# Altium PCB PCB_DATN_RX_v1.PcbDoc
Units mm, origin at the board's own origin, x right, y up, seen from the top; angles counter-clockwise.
Board outline 70.3 x 45.3 mm, 2 copper layers (Top Layer, Bottom Layer); 34 components, 25 nets, 155 pads, 46 vias.
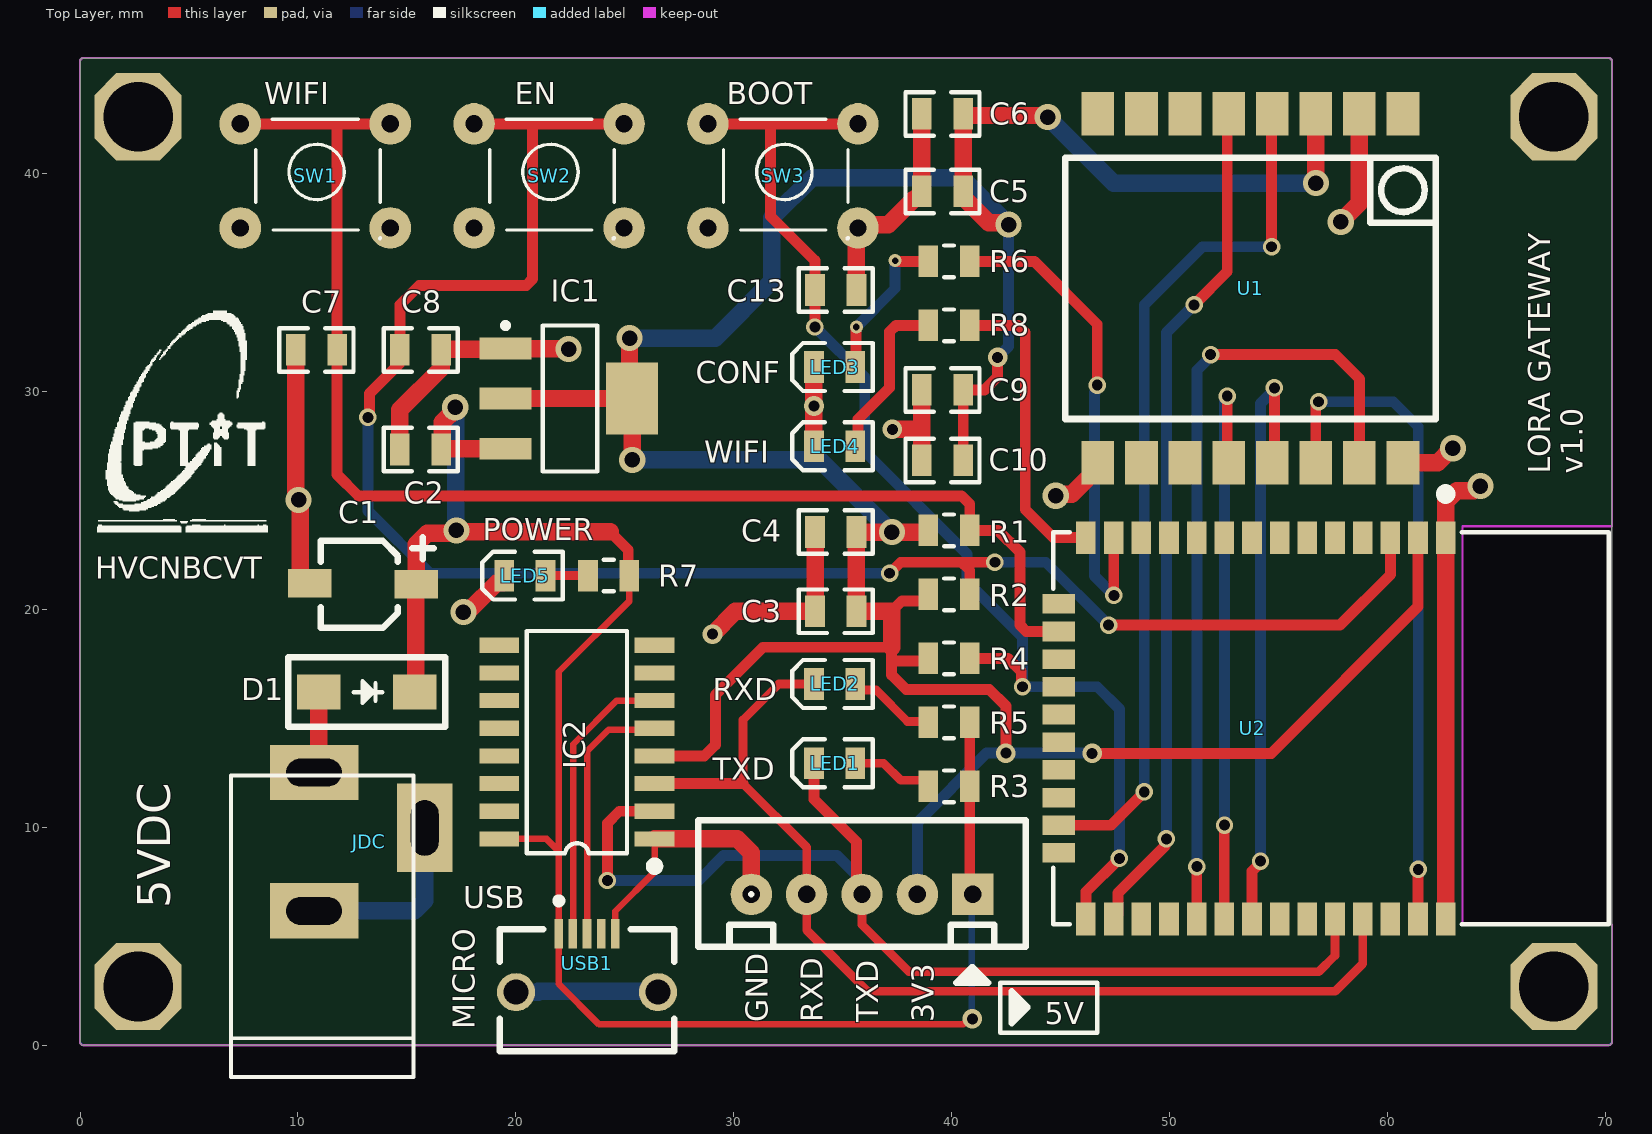
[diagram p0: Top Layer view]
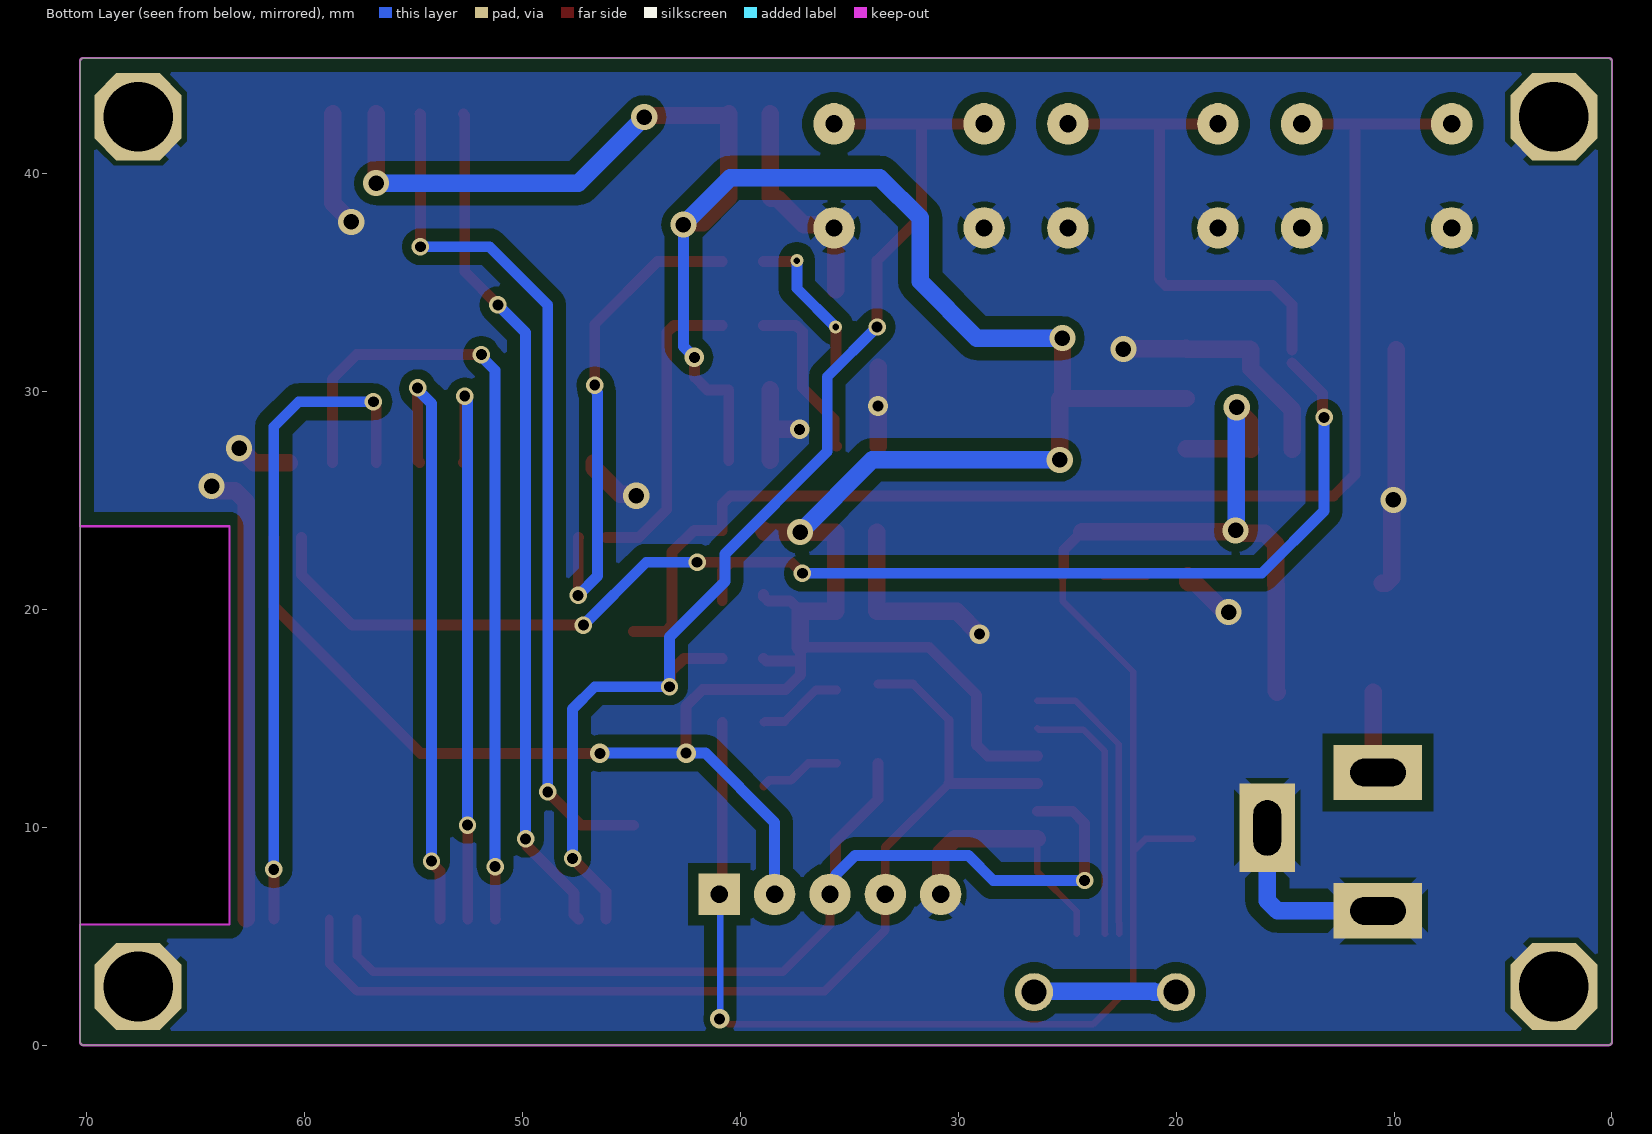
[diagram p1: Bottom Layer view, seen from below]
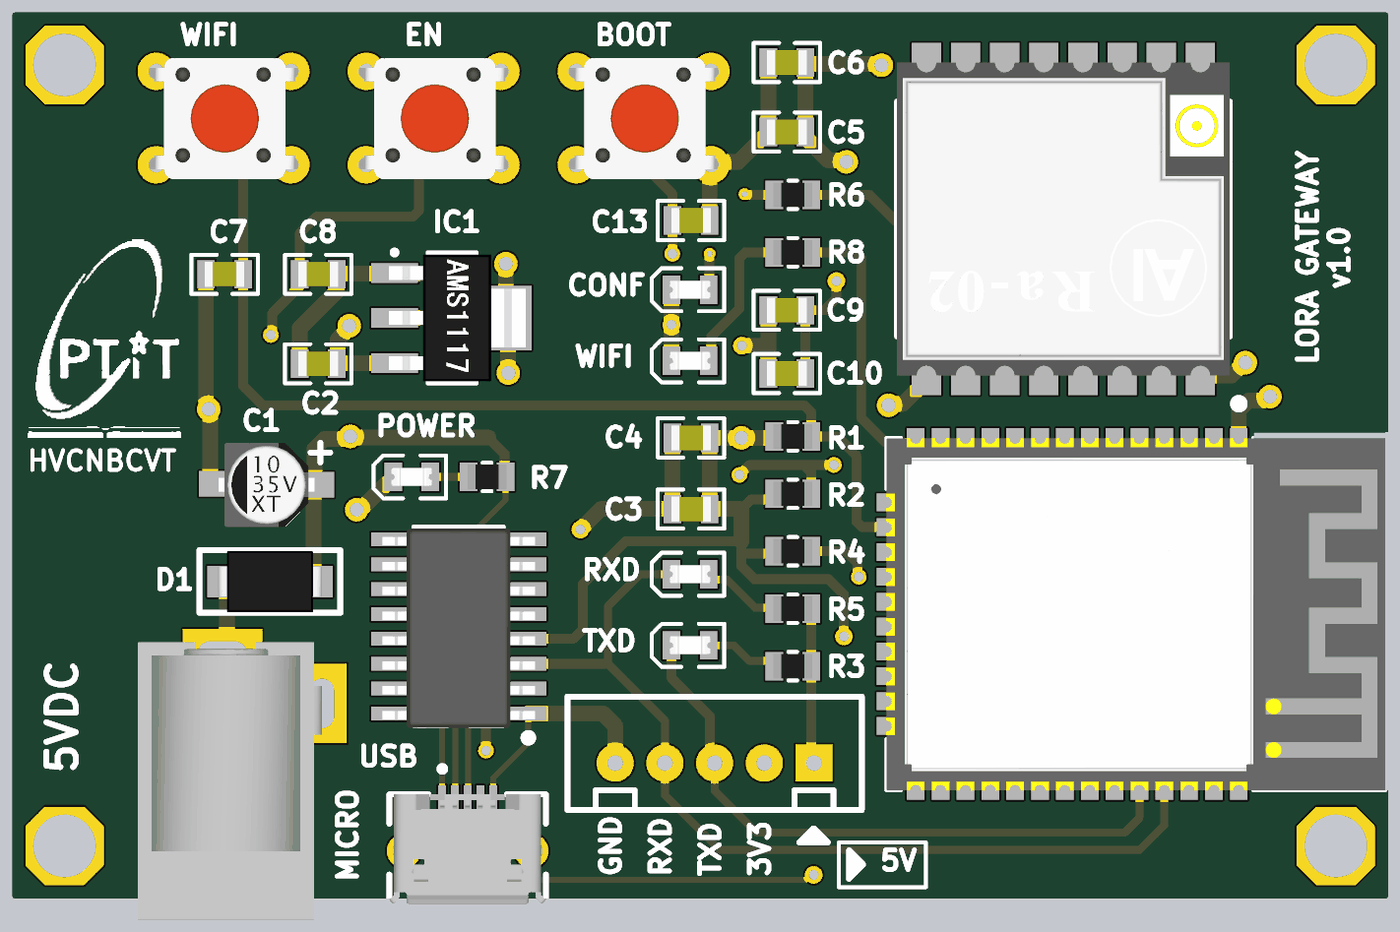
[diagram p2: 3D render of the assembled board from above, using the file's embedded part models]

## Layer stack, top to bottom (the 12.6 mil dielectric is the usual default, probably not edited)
Top Solder: solder mask 0.0102, Solder Resist, Dk 3.5
Top Layer: signal copper 0.0356
Dielectric 1: dielectric 0.32, FR-4, Dk 4.8
Bottom Layer: signal copper 0.0356
Bottom Solder: solder mask 0.0102, Solder Resist, Dk 3.5

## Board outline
0,0.15 ccw(c0.15,0.15) 0.15,0 70.15,0 ccw(c70.15,0.15) 70.301,0.15 70.301,45.15 ccw(c70.15,45.15) 70.15,45.301 0.15,45.301 ccw(c0.15,45.15) 0,45.15
cut-out: 70.301,23.814 63.443,23.814 63.443,5.526 70.301,5.526

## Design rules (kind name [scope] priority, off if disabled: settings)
Clearance [All] p1: gap=0.254 ignorepadtopadclearanceinfootprint=FALSE except(0.3: SMDPad-Fill SMDPad-Poly SMDPad-Region Via-Fill Via-Poly Via-Region Fill-Fill Fill-Poly Fill-Region Poly-Poly Poly-Region Region-Region; 0.5: THPad-Fill THPad-Poly THPad-Region; 0.6: Arc-Fill Arc-Poly Arc-Region Track-Fill Track-Poly Track-Region)
DiffPairsRouting [InDifferentialPair('USB_TX')] p1: maxlimit=0.508 minlimit=0.254 mostfreqgap=0.381 toplayer_minwidth=0.3 toplayer_maxwidth=0.5 toplayer_prefwidth=0.4 bottomlayer_minwidth=0.3 bottomlayer_maxwidth=0.5 bottomlayer_prefwidth=0.4 maxuncoupledlength=12.7
PolygonConnect POLY_VIA [IsVia] p1: connectstyle=Direct reliefconductorwidth=0.254 reliefentries=4 polygonreliefangle="90 Angle" airgapwidth=0.254
PolygonConnect [All] p2: connectstyle=Relief reliefconductorwidth=0.762 reliefentries=4 polygonreliefangle="45 Angle" airgapwidth=0.254
RoutingVias VIA_POWER [InNetClass('POWER')] p1: holewidth=0.6 width=1 viastyle="Through Hole" minholewidth=0.5 minwidth=0.9 maxholewidth=0.8 maxwidth=1.2
RoutingVias [All] p2: holewidth=0.4 width=0.7 viastyle="Through Hole" minholewidth=0.3 minwidth=0.6 maxholewidth=0.5 maxwidth=0.8
SolderMaskExpansion [All] p1: expansion=0.102 istentingtop=FALSE
Width LORA [InNetClass('LORA')] p1: maxlimit=0.5 minlimit=0.3 preferedwidth=0.4
Width UART [InNetClass('UART')] p2: maxlimit=0.5 minlimit=0.3 preferedwidth=0.4
Width POWER [InNetClass('POWER')] p3: maxlimit=0.8 minlimit=0.3 preferedwidth=0.5
Width [All] p4: maxlimit=0.8 minlimit=0.4 preferedwidth=0.6
29 further rules are at their usual default settings.

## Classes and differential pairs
net class UART: RXD TXD
net class LORA: DIO0 MISO MOSI NSS RST SCLK
net class USB: USB_TX_N USB_TX_P
net class POWER: 3V3 5V GND NetD1_1
differential pair USB_TX: +USB_TX_P -USB_TX_N

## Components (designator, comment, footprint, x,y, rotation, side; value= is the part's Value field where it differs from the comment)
C1 "22uF/16V" "Cap Aluminum 4x5.4" 12.887,21.447 r0 top
C2 "100nF" "CAP SMD 0805" 14.68,27.335 r0 top value=103
C3 "100nF" "CAP SMD 0805" 33.73,19.912 r0 top value=103
C4 "10uF" "CAP SMD 0805" 33.73,23.549 r0 top value=103
C5 "100nF" "CAP SMD 0805" 38.629,39.181 r0 top value=103
C6 "10uF" "CAP SMD 0805" 38.629,42.737 r0 top value=103
C7 "100nF" "CAP SMD 0805" 9.896,31.907 r0 top value=103
C8 "100nF" "CAP SMD 0805" 16.58,31.907 r180 top value=103
C9 "100nF" "CAP SMD 0805" 38.629,30.071 r0 top value=103
C10 "10uF" "CAP SMD 0805" 38.629,26.834 r0 top value=103
C13 "100nF" "CAP SMD 0805" 35.63,34.657 r180 top value=103
D1 "Diode" "DIODE SMA" 13.151,16.194 r0 top
IC1 "AMS1117-SOT223" AMS1117-SOT223 22.029,29.875 r270 top
IC2 "CH340C" SOP-16 22.803,13.908 r180 top
JDC "JACK DC 5.5" "DC IN" 13.278,9.336 r90 top
LED1 "LED" "LED SMD 0805" 35.58,12.94 r180 top value="LED 3 ly Single Colour"
LED2 "LED" "LED SMD 0805" 35.58,16.576 r180 top value="LED 3 ly Single Colour"
LED3 "LED" "LED SMD 0805" 35.58,31.121 r180 top value="LED 3 ly Single Colour"
LED4 "LED" "LED SMD 0805" 35.58,27.485 r180 top value="LED 3 ly Single Colour"
LED5 "LED" "LED SMD 0805" 21.359,21.55 r180 top value="LED 3 ly Single Colour"
R1 "10K" "RES SMD 0805" 40.828,23.624 r180 top value=1K
R2 "10K" "RES SMD 0805" 40.828,20.687 r180 top value=1K
R3 "2K" "RES SMD 0805" 38.928,11.876 r0 top value=1K
R4 "10K" "RES SMD 0805" 40.828,17.75 r180 top value=1K
R5 "2K" "RES SMD 0805" 38.928,14.813 r0 top value=1K
R6 "1K" "RES SMD 0805" 40.828,35.971 r180 top
R7 "1K" "RES SMD 0805" 25.211,21.55 r180 top
R8 "1K" "RES SMD 0805" 40.828,33.035 r180 top
SW1 "SW 4 PIN" "SW 4 PIN TH" 10.857,40.073 r0 top
SW2 "SW 4 PIN" "SW 4 PIN TH" 21.589,40.073 r0 top
SW3 "SW 4 PIN" "SW 4 PIN TH" 32.32,40.073 r0 top
U1 "Module Ra-02" "module ra02" 60.71,42.735 r270 top
U2 "ESP32-WROOM-32" ESP32-WROOM-32 53.791,14.543 r270 top
USB1 "Micro USB" "MICRO USB CONNECTOR" 23.264,3.77 r0 top

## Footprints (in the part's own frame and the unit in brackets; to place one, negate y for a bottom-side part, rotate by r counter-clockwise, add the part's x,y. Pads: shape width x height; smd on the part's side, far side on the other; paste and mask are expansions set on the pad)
AMS1117-SOT223 [mm]
  rect 1x2.4 smd: 1(-2.1,-2.5) 2(0.2,-2.5) 3(2.5,-2.5)
  rect 3.3x2.4 smd: 4(0.2,3.3)
  silkscreen extent -3.27,-2.62 3.55,1.7, body extent -3.05,-2.8 3.45,4.2, height 1.85
"Cap Aluminum 4x5.4" [mm]
  rect 2x1.3 smd: 1(2.55,-0.3) 2(-2.35,-0.25)
  silkscreen extent -1.85,-2.3 3.35,1.85, body extent -2.35,-2.45 2.55,1.85, height 6.4
"CAP SMD 0805" [mm]
  rect 0.9x1.45 smd: 1(0,0) 2(1.9,0)
  silkscreen extent -0.75,-1 2.65,1, body extent -0.06,-0.64 1.96,0.64, height 0.61
"DC IN" [mil]
  rect 100x160 hole 50 slot 100 at 90 deg: 1(125,100) 2(-125,100)
  rect 160x100 hole 50 slot 100 at 0 deg: 3(25,-100)
  silkscreen extent -425,-80 120,250, body extent -410,-100 149,270, height 453
"DIODE SMA" [mm]
  rect 2x1.6 smd: 1(-2.19,0.01) 2(2.21,0.01)
  silkscreen extent -3.59,-1.59 3.61,1.61, body extent -2.64,-1.54 2.66,1.57, height 2.4
ESP32-WROOM-32 [mm]
  rect 1.5x0.9 smd: 1(-8.75,8.88) 2(-8.75,7.61) 3(-8.75,6.34) 4(-8.75,5.07) 5(-8.75,3.8) 6(-8.75,2.53) 7(-8.75,1.26) 8(-8.75,-0.01) 9(-8.75,-1.28) 10(-8.75,-2.55) 11(-8.75,-3.82) 12(-8.75,-5.09) 13(-8.75,-6.36) 14(-8.75,-7.63) 25(8.75,-7.63) 26(8.75,-6.36) 27(8.75,-5.09) 28(8.75,-3.82) 29(8.75,-2.55) 30(8.75,-1.28) 31(8.75,-0.01) 32(8.75,1.26) 33(8.75,2.53) 34(8.75,3.8) 35(8.75,5.07) 36(8.75,6.34) 37(8.75,7.61) 38(8.75,8.88)
  rect 0.9x1.5 smd: 15(-5.71,-8.88) 16(-4.44,-8.88) 17(-3.17,-8.88) 18(-1.9,-8.88) 19(-0.63,-8.88) 20(0.64,-8.88) 21(1.91,-8.88) 22(3.18,-8.88) 23(4.45,-8.88) 24(5.72,-8.88)
  silkscreen extent -10.95,-9.13 9,16.37, body extent -9,-9.15 9.04,16.37, height 3.15
"LED SMD 0805" [mm]
  rect 0.9x1.45 smd: 1(0,0) 2(1.9,0)
  silkscreen extent -0.8,-1.1 2.9,1.1, body extent -0.08,-0.46 1.98,0.45, height 0.85
"MICRO USB CONNECTOR" [mm]
  rect 0.4x1.35 smd: 1(-1.3,1.338) 2(-0.65,1.338) 3(0,1.338) 4(0.65,1.338) 5(1.3,1.338)
  round 1.75 hole 1.15: 6(-3.255,-1.337) 7(3.255,-1.337)
  silkscreen extent -4,-4.05 4,2.9, body extent -4,-4.05 4,1.55, height 2.68
"module ra02" [mm]
  rect 2x1.5 smd: 1(0,0) 2(0,-2) 3(0,-4) 4(0,-6) 5(0,-8) 6(0,-10) 7(0,-12) 8(0,-14) 9(16,-14) 10(16,-12) 11(16,-10) 12(16,-8) 13(16,-6) 14(16,-4) 15(16,-2) 16(16,0)
  silkscreen extent 2,-15.5 14,1.5, body extent 0,-15.5 16,1.5, height 3.2
"RES SMD 0805" [mm]
  rect 0.9x1.45 smd: 1(0,0) 2(1.9,0)
  silkscreen extent 0.72,-0.73 1.17,0.73, body extent -0.05,-0.63 1.95,0.63, height 0.58
SOP-16 [mm]
  rect 1.825x0.7 smd: 1(-3.562,4.445) 2(-3.562,3.175) 3(-3.562,1.905) 4(-3.562,0.635) 5(-3.562,-0.635) 6(-3.562,-1.905) 7(-3.562,-3.175) 8(-3.562,-4.445) 9(3.562,-4.445) 10(3.562,-3.175) 11(3.562,-1.905) 12(3.562,-0.635) 13(3.562,0.635) 14(3.562,1.905) 15(3.562,3.175) 16(3.562,4.445)
  silkscreen extent -3.76,-5.1 2.3,5.89, body extent -3.9,-5.01 3.9,5.19, height 2
"SW 4 PIN TH" [mil]
  round 75 hole 31: 1(-138,87) 2(133,-101) 3(133,87) 4(-138,-101)
  silkscreen extent -110,-120 115,95, body extent -156,-130 156,114, height 276

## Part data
C1: library part "Capacitor Polarity", "CAP ALUMINUM"
C2 C3 C5 C7 C8 C9 C13: library part CM, "CM 0805"
C4 C6 C10: library part CM, "Cap SMD"
IC1: library part AMS1117
JDC: library part "DC IN 5.5"
LED1 LED2 LED3 LED4 LED5: "LED Single colour Green and Red"
R1 R2 R3 R4 R5 R6 R7 R8: library part RM, "Resistor SMD"
U1: library part "Module Ra02"
USB1: library part "Micro USB Connector"

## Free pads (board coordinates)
  rect 1.9x1.9 hole 0.8: 1(40.964,6.923)
  round 1.9 hole 0.8: 2(38.424,6.923) 3(35.884,6.923) 4(33.344,6.923) 5(30.804,6.923)
  oct 4x4 hole 3.2: 3(2.666,2.69) 3(2.666,42.61) 3(67.634,2.69) 3(67.634,42.61)

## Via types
v1: diameter 0.8, hole 0.5, Top Layer to Bottom Layer, 22 vias
v2: diameter 1.2, hole 0.711, Top Layer to Bottom Layer, 15 vias
v3: diameter 0.9, hole 0.5, Top Layer to Bottom Layer, 7 vias
v4: diameter 0.6, hole 0.3, Top Layer to Bottom Layer, 2 vias

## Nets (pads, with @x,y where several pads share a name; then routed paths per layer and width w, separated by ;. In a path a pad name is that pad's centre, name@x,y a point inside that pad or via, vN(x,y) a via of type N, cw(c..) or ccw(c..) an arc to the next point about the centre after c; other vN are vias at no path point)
3V3: C3.2 C4.2 C5.2 C6.2 C9.2 C10.2 IC1.2 IC1.4 IC2.4 pad.2 R1.2 R2.2 R4.2 U1.3 U2.2 | length 158.3
  Top Layer w0.5: IC2.4 28.645,13.273 29.153,13.781 29.153,16.067 31.346,18.26 37.248,18.26 37.248,17.625 ; 37.248,19.912 37.728,20.392 38.728,20.392 38.928,20.592 R2.2 ; R4.2 38.803,17.625 37.248,17.625 ; C10.2 C9.2 41.506,30.071 42.107,30.672 v3(42.107,31.561) ; v3(42.488,13.4) 42.488,15.559 41.726,16.321 37.916,16.321 37.248,16.99 37.248,17.625 ; v3(46.447,13.393) 54.668,13.393 61.401,20.126 U2.2
  Top Layer w0.8: IC1.2 IC1.4 ; v2(25.216,32.45) 25.216,29.788 IC1.4 ; v2(25.343,26.862) 25.336,26.87 25.336,29.668 IC1.4 ; 37.248,18.26 37.248,19.912 C3.2 C4.2 v2(37.254,23.549) 38.878,23.549 38.928,23.599 R1.2 ; C6.2 C6.2@40.529,42.715 ; v2(42.615,37.657) 42.539,37.734 41.702,37.734 40.529,38.906 C5.2 C6.2@40.529,42.715 ; v2(44.409,42.594) 44.337,42.665 40.579,42.665 C6.2@40.529,42.715 ; U1.3 56.71,39.565 v2(56.712,39.562)
  Bottom Layer w0.5: pad.2 38.424,10.225 41.599,13.4 46.44,13.4 v3(46.447,13.393) ; v3(42.107,31.561) 42.615,32.069 v2(42.615,37.657)
  Bottom Layer w0.8: v2(25.216,32.45) 29.153,32.45 31.75,35.047 31.75,37.973 33.593,39.816 40.456,39.816 v2(42.615,37.657) ; v2(25.343,26.862) 33.94,26.862 v2(37.254,23.549) ; v2(44.409,42.594) 47.441,39.562 v2(56.712,39.562)
5V: C1.1 C2.2 D1.2 IC1.3 IC2.16 pad.1 R3.2 R5.2 R7.1 USB1.1 | length 85.6
  Top Layer w0.3: IC2.16 21.406,9.463 21.914,8.955 ; R7.1 25.211,20.38 21.964,17.133 21.964,8.955 USB1.1 21.964,2.809 23.819,0.954 40.533,0.954 40.787,1.208 v3(40.95,1.208)
  Top Layer w0.5: 24.327,23.56 25.157,22.731 25.157,21.605 R7.1 ; R5.2 R3.2 40.828,7.06 pad.1
  Top Layer w0.8: D1.2 15.399,16.242 15.399,21.109 C1.1 15.437,22.997 15.924,23.484 17.026,23.484 17.164,23.622 v2(17.272,23.622) 17.334,23.56 24.327,23.56 ; C2.2 C2.2@16.62,27.375 ; v2(17.215,29.275) 17.215,29.167 16.63,28.582 16.63,27.385 C2.2@16.62,27.375 ; IC1.3 C2.2@16.62,27.375
  Bottom Layer w0.3: v3@40.914,1.244 40.914,6.873 pad.1
  Bottom Layer w0.8: v2(17.215,29.275) 17.244,29.247 17.244,23.65 v2(17.272,23.622)
CONF: C7.2 R1.1 SW1.1 SW1.3 U2.16 | length 61.8
  Top Layer w0.5: SW1.1 11.796,42.283 ; SW1.3 11.796,42.283 ; U2.16 43.421,18.983 43.128,19.276 43.128,22.627 42.132,23.624 R1.1 40.828,24.84 40.456,25.211 12.77,25.211 11.796,26.186 11.796,42.283
DIO0: U1.5 U2.26 | length 39.1
  Top Layer w0.5: U2.26 47.631,5.993 47.631,6.978 49.797,9.144 49.797,9.406 v1(49.854,9.463) ; v1(51.124,33.974) 52.648,35.498 52.648,42.674 U1.5
  Bottom Layer w0.5: v1(49.854,9.463) 49.854,32.704 v1(51.124,33.974)
EN: C8.2 R2.1 SW2.1 SW2.3 U2.3 | length 84.1
  Top Layer w0.5: v1(13.21,28.809) 13.267,28.866 13.267,29.078 13.278,29.089 13.278,29.905 C8.2@14.68,31.307 ; C8.2 14.68,33.979 15.564,34.863 20.478,34.863 20.771,35.156 20.771,42.283 ; SW2.1 20.771,42.283 ; SW2.3 20.771,42.283 ; v1(37.154,21.655) 37.662,22.163 40.456,22.163 ; R2.1@40.828,20.412 R2.1 40.828,21.792 40.456,22.163 ; v1(41.98,22.163) 40.456,22.163 ; v1(47.2,19.281) 57.821,19.281 60.131,21.591 U2.3
  Bottom Layer w0.5: v1(13.21,28.809) 13.21,24.518 16.072,21.655 v1(37.154,21.655) ; v1(41.98,22.163) 44.317,22.163 v1(47.2,19.281)
GND: C1.2 C2.1 C3.1 C4.1 C5.1 C6.1 C7.1 C8.1 C9.1 C10.1 C13.1 IC1.1 IC2.1 JDC.2 JDC.3 LED3.2 LED4.2 LED5.2 pad.3@2.666,2.69 pad.3@2.666,42.61 pad.3@67.634,2.69 pad.3@67.634,42.61 pad.5 SW1.2 SW1.4 SW2.2 SW2.4 SW3.2 SW3.4 U1.2 U1.9 U1.16 U2.1 U2.38 USB1.5 | length 104.4
  Top Layer w0.3: USB1.5 24.564,6.144 26.365,7.945 IC2.1
  Top Layer w0.8: C7.1 9.896,25.264 10.033,25.127 v2(10.033,25.019) 10.11,24.942 10.11,21.447 10.36,21.197 C1.2 ; C2.1 14.68,29.153 16.58,31.053 C8.1 16.614,31.941 19.495,31.941 IC1.1 19.545,31.959 22.406,31.959 v2(22.422,31.942) ; v2(17.596,19.877) 17.673,19.954 17.863,19.954 19.134,21.225 19.409,21.225 19.459,21.275 LED5.2 ; IC2.1 30.169,9.463 30.804,8.828 pad.5 ; v3(29.026,18.861) 30.077,19.912 C3.1 C4.1 ; LED4.2 v3(33.68,29.333) LED3.2 ; C13.1 35.63,37.439 35.842,37.651 37.099,37.651 38.304,38.856 38.579,38.856 38.629,38.906 C6.1 ; v3(37.281,28.259) 38.629,28.259 ; C10.1 38.629,28.259 ; C9.1 38.629,28.259 ; v2(44.774,25.211) 44.851,25.288 45.512,25.288 46.71,26.485 U1.9 ; v2(57.855,37.784) 58.71,38.639 U1.2 ; U1.16 62.3,26.735 62.935,27.37 62.986,27.37 v2(63.006,27.391) ; U2.38 62.671,24.947 63.174,25.45 63.95,25.45 64.154,25.654 v2(64.262,25.654)
  Bottom Layer w0.8: JDC.2 15.35,6.161 15.818,6.63 JDC.3
  Bottom Layer w1: JDC.3@15.691,9.844 JDC.3
IO0: C13.2 R4.1 SW3.1 SW3.3 U2.25 | length 56
  Top Layer w0.5: SW3.1 31.566,42.283 ; v1(33.725,32.958) 33.73,32.963 C13.2 33.73,36.001 31.693,38.038 31.693,42.156 31.566,42.283 ; SW3.3 31.566,42.283 ; R4.1 42.584,17.75 43.193,17.141 43.193,16.506 v1(43.25,16.448) ; U2.25 46.161,7.04 v1(47.695,8.574)
  Bottom Layer w0.5: v1(33.725,32.958) 36.011,30.672 36.011,27.243 40.71,22.544 40.71,21.274 43.25,18.734 v1(43.25,16.448) 46.679,16.448 47.695,15.432 v1(47.695,8.574)
LED_CONF: R6.1 U2.13 | length 22.6
  Top Layer w0.5: R6.1 43.793,35.971 46.679,33.085 v1(46.679,30.291) ; U2.13 47.436,23.288 47.436,20.644 v1(47.441,20.639)
  Bottom Layer w0.5: v1(46.679,30.291) 46.622,30.234 46.622,30.022 46.552,29.952 46.552,21.528 v1(47.441,20.639)
LED_WF: R8.1 U2.14 | length 14.1
  Top Layer w0.5: R8.1 43.047,33.035 43.377,32.704 43.377,24.576 44.66,23.293 U2.14
MISO: U1.13 U2.31 | length 28.3
  Top Layer w0.5: U2.31 53.786,5.798 53.786,7.98 54.172,8.366 v1(54.172,8.447) ; U1.13 54.807,26.833 v1(54.807,30.164)
  Bottom Layer w0.5: v1(54.172,8.447) 54.172,29.448 54.807,30.083 v1(54.807,30.164)
MOSI: U1.14 U2.37 | length 30.5
  Top Layer w0.5: U1.14 56.71,29.319 56.839,29.448 v1(56.839,29.529) ; U2.37 61.406,5.798 61.406,8.061 v1(61.411,8.066)
  Bottom Layer w0.5: v1(56.839,29.529) 60.264,29.529 61.411,28.382 61.411,27.751 v1(61.411,8.066)
NetD1_1: D1.1 JDC.1 | length 3.8
  Top Layer w0.8: JDC.1 10.961,12.734 D1.1
NetLED1_1: LED1.1 R3.1 | length 3.8
  Top Layer w0.4: LED1.1 36.874,12.94 37.662,12.151 38.678,12.151 38.928,11.901 R3.1
NetLED2_1: LED2.1 R5.1 | length 4
  Top Layer w0.4: LED2.1@35.585,16.297 36.535,16.297 37.976,14.856 38.885,14.856 R5.1
NetLED3_1: LED3.1 R6.2 | length 7.5
  Top Layer w0.5: LED3.1@35.58,31.396 LED3.1 35.611,31.152 35.611,32.939 v4(35.63,32.958) ; v4(37.408,36.006) 37.435,36.006 37.47,35.971 R6.2
  Bottom Layer w0.5: v4(35.63,32.958) 37.408,34.736 v4(37.408,36.006)
NetLED4_1: LED4.1 R8.2 | length 7.8
  Top Layer w0.5: LED4.1 35.709,27.613 35.709,28.724 37.154,30.169 37.154,32.742 37.447,33.035 R8.2
NetLED5_1: LED5.1 R7.2 | length 2
  Top Layer w0.4: LED5.1 R7.2
NetUSB1_6: USB1.6 USB1.7 | length 7.3
  Top Layer w0.6: USB1.6 20.217,2.432 20.39,2.605 20.39,2.583 USB1.6@20.541,2.432
  Bottom Layer w0.8: USB1.6 21.025,2.432 21.025,2.478 26.519,2.478 USB1.7
NSS: U1.15 U2.29 | length 37.3
  Top Layer w0.5: U2.29 51.246,5.798 51.246,8.188 v1(51.251,8.193) ; v1(51.886,31.688) 57.601,31.688 58.71,30.58 U1.15
  Bottom Layer w0.5: v1(51.251,8.193) 51.251,30.972 51.886,31.607 v1(51.886,31.688)
RST: U1.4 U2.23 | length 40
  Top Layer w0.5: U2.23 47.309,10.093 v1(48.838,11.622) ; v1(54.68,36.641) 54.68,42.706 U1.4
  Bottom Layer w0.5: v1(48.838,11.622) 48.838,33.974 51.505,36.641 v1(54.68,36.641)
RXD: IC2.3 LED2.2 pad.4 U2.35 | length 48.1
  Top Layer w0.4: LED2.2 32.075,16.576 30.423,14.924 30.423,12.003 33.344,9.082 pad.4 33.344,5.272 36.138,2.478 57.601,2.478 58.861,3.738 U2.35
  Top Layer w0.5: IC2.3 30.423,12.003
SCLK: U1.12 U2.30 | length 27.1
  Top Layer w0.5: U2.30 52.511,10.088 v1(52.521,10.098) ; v1(52.648,29.783) 52.648,26.797 U1.12
  Bottom Layer w0.5: v1(52.521,10.098) 52.521,29.575 52.648,29.702 v1(52.648,29.783)
TXD: IC2.2 LED1.2 pad.3@35.884,6.923 U2.34 | length 51.2
  Top Layer w0.4: pad.3@35.884,6.923 35.884,5.526 38.043,3.367 56.839,3.367 57.591,4.119 U2.34
  Top Layer w0.5: v1(24.2,7.558) 24.2,10.186 24.747,10.733 IC2.2 ; LED1.2 33.68,11.286 35.63,9.336 35.63,7.177 pad.3@35.884,6.923
  Bottom Layer w0.5: v1(24.2,7.558) 28.391,7.558 29.534,8.701 34.741,8.701 35.617,7.826 35.617,7.191 pad.3@35.884,6.923
USB_TX_N: IC2.6 USB1.2 | length 13.3
  Top Layer w0.3: USB1.2 22.614,5.617 22.63,5.632 22.63,13.809 24.634,15.813 IC2.6
USB_TX_P: IC2.5 USB1.3 | length 11.9
  Top Layer w0.3: USB1.3 23.28,5.123 23.28,13.496 24.255,14.471 26.293,14.471 IC2.5
pads on no net: IC2.7 IC2.8 IC2.9 IC2.10 IC2.11 IC2.12 IC2.13 IC2.14 IC2.15 U1.1 U1.6 U1.7 U1.8 U1.10 U1.11 U2.4 U2.5 U2.6 U2.7 U2.8 U2.9 U2.10 U2.11 U2.12 U2.15 U2.17 U2.18 U2.19 U2.20 U2.21 U2.22 U2.24 U2.27 U2.28 U2.32 U2.33 U2.36 USB1.4

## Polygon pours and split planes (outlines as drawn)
GND on Bottom Layer "GND_L02_P000" (solid, remove dead copper, pour order 0): 0,45.15 0,0.15 70.15,0.15 70.15,45.301

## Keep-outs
Keep-Out Layer:
  lines w0.1: 70.301,5.526 70.301,0.15 ; 70.301,5.543 63.443,5.543 63.443,23.814 70.301,23.814 70.301,45.15 ; 0,45.15 cw(c0.15,45.15) 0.15,45.301 ; 0,45.15 cw(c0.15,45.15) 0.15,45.301 ; 0,45.15 0,0.15 ccw(c0.15,0.15) 0.15,0 70.15,0 ; 0.15,45.301 70.15,45.301 ; 0.15,45.301 70.15,45.301 ; 70.15,0 ccw(c70.15,0.15) 70.301,0.15 ; 70.15,0 ccw(c70.15,0.15) 70.301,0.15 ; 70.15,45.301 cw(c70.15,45.15) 70.301,45.15 ; 70.15,45.301 cw(c70.15,45.15) 70.301,45.15 ; 70.301,0.15 70.301,0.15 ; 70.301,45.15 70.301,45.15

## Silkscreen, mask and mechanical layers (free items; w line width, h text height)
Top Overlay:
  drawing of 1063 lines, arcs and shapes, not listed
  text "WIFI" at 8.461,43.172 h1
  text "EN" at 19.942,43.172 h1
  text "BOOT" at 29.674,43.172 h1
  text "CONF" at 28.264,30.371 h1
  text "WIFI" at 28.645,26.735 h1
  text "LORA GATEWAY / v1.0" at 68.96,26.225 h1 r90
  text "POWER" at 18.485,23.179 h1
  text "HVCNBCVT" at 0.705,21.401 h1
  text "RXD" at 29.026,15.826 h1
  text "TXD" at 29.026,12.19 h1
  text "5VDC" at 4.134,6.288 h1.5 r90
  text "USB" at 17.596,6.288 h1
  text "GND" at 31.554,1.059 h1 r90
  text "RXD" at 34.094,1.059 h1 r90
  text "TXD" at 36.634,1.059 h1 r90
  text "3V3" at 39.174,1.059 h1 r90
  text "5V" at 44.266,0.967 h1
  text "MICRO" at 18.104,0.741 h1 r90
Top TOP-BOT:
  circle w0.05: c33.344,6.923 r0.95
  circle w0.05: c35.884,6.923 r0.95
  circle w0.05: c38.424,6.923 r0.95
  circle w0.05: c30.804,6.923 r0.95
  lines w0.05: 40.004,5.973 40.004,7.873 41.904,7.873 41.904,5.973 40.004,5.973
